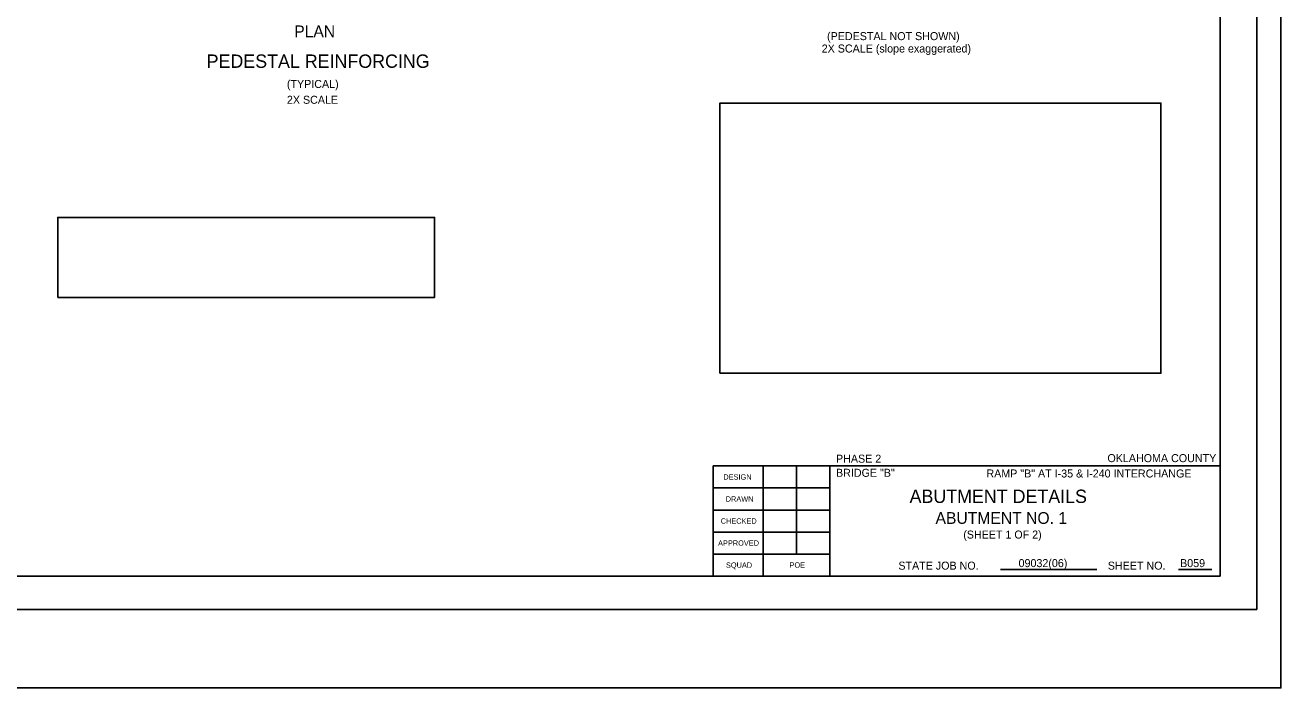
# Model space of a CAD drawing. Extents: x 2146724 to 2153191, y 139029 to 143935.
# Drawn here: x 2146992.9 to 2147068.3, y 143589.8 to 143629.5 of the extents above; entities that cross this region are included whole.
import ezdxf

# ---------------------------------------------------------------- set-up
doc = ezdxf.new("R2010")
doc.units = 0
for name, color, linetype in [('PR_Dimensions', 7, 'Continuous'), ('SHT_Plot_Shape_Full', 7, 'Continuous'), ('SHT_Plot_Shape_Half', 7, 'Continuous'), ('SHT_Sheet_Border', 7, 'Continuous'), ('SHT_Standard_Sheet_Lines', 7, 'Continuous'), ('SHT_Standard_Sheet_Txt', 7, 'Continuous'), ('T', 7, 'Continuous'), ('T-Subtitle', 7, 'Continuous'), ('T-Title', 7, 'Continuous')]:
    doc.layers.add(name, color=color, linetype=linetype)

msp = doc.modelspace()

# ---------------------------------------------------------------- linework, layer by layer
at = {"layer": 'PR_Dimensions'}
for points in [[(2147034.603, 143608.631), (2147061.061, 143608.631), (2147061.061, 143624.83), (2147034.603, 143624.83)], [(2146994.891, 143613.183), (2147017.495, 143613.183), (2147017.495, 143617.975), (2146994.891, 143617.975)]]:
    msp.add_lwpolyline(points, close=True, dxfattribs=at)
at = {"layer": 'SHT_Plot_Shape_Full'}
msp.add_lwpolyline([(2146924.253, 143685.779), (2147068.253, 143685.779), (2147068.253, 143589.779), (2146924.253, 143589.779)], close=True, dxfattribs=at)
at = {"layer": 'SHT_Plot_Shape_Half'}
msp.add_lwpolyline([(2146930.803, 143682.479), (2147066.803, 143682.479), (2147066.803, 143594.479), (2146930.803, 143594.479)], close=True, dxfattribs=at)
at = {"layer": 'SHT_Sheet_Border'}
for p, q in [((2147034.203, 143596.479), (2147034.203, 143603.079)), ((2147034.203, 143603.079), (2147064.603, 143603.079)), ((2147041.203, 143596.479), (2147041.203, 143603.082)), ((2147041.203, 143596.479), (2147041.203, 143603.082))]:
    msp.add_line(p, q, dxfattribs=at)
msp.add_lwpolyline([(2147064.603, 143596.479), (2146938.603, 143596.479), (2146938.603, 143680.479), (2147064.603, 143680.479)], close=True, dxfattribs=at)
at = {"layer": 'SHT_Standard_Sheet_Lines'}
for p, q in [((2147037.203, 143596.479), (2147037.203, 143603.082)), ((2147039.203, 143597.8), (2147039.203, 143603.082)), ((2147051.446, 143596.864), (2147057.207, 143596.864)), ((2147051.446, 143596.864), (2147057.207, 143596.864)), ((2147062.105, 143596.864), (2147064.115, 143596.864)), ((2147062.105, 143596.864), (2147064.115, 143596.864))]:
    msp.add_line(p, q, dxfattribs=at)
for points in [[(2147041.203, 143601.759), (2147034.203, 143601.759)], [(2147041.203, 143600.439), (2147034.203, 143600.439)], [(2147041.203, 143599.119), (2147034.203, 143599.119)], [(2147041.203, 143597.799), (2147034.203, 143597.799)]]:
    msp.add_lwpolyline(points, dxfattribs=at)

# ---------------------------------------------------------------- texts
at = {"layer": 'Defpoints'}
for s, p in [('2X SCALE (slope exaggerated)', (2147040.713, 143627.858)), ('2X SCALE', (2147008.637, 143624.786))]:
    msp.add_text(s, height=0.48, dxfattribs=at).set_placement(p)
at = {"layer": 'SHT_Standard_Sheet_Txt'}
for s, height, p in [('DESIGN', 0.32, (2147034.812, 143602.259)), ('DRAWN', 0.32, (2147034.955, 143600.938)), ('CHECKED', 0.32, (2147034.654, 143599.618)), ('APPROVED', 0.32, (2147034.497, 143598.297)), ('SQUAD', 0.32, (2147034.969, 143596.976)), ('POE', 0.32, (2147038.783, 143596.979)), ('STATE JOB NO.', 0.48, (2147045.311, 143596.864)), ('STATE JOB NO.', 0.48, (2147045.311, 143596.864)), ('SHEET NO. ', 0.48, (2147057.872, 143596.864)), ('SHEET NO. ', 0.48, (2147057.872, 143596.864))]:
    msp.add_text(s, height=height, dxfattribs=at).set_placement(p)
at = {"layer": 'T'}
for s, height, p in [('(PEDESTAL NOT SHOWN)', 0.48, (2147041.034, 143628.601)), ('(TYPICAL)', 0.48, (2147008.637, 143625.734)), ('PHASE 2', 0.48, (2147041.571, 143603.276)), ('OKLAHOMA COUNTY', 0.48, (2147057.85, 143603.308)), ('BRIDGE "B"', 0.48, (2147041.571, 143602.429)), ('RAMP "B" AT I-35 & I-240 INTERCHANGE', 0.48, (2147050.592, 143602.388)), ('(SHEET 1 OF 2)', 0.47917, (2147049.205, 143598.728)), ('09032(06)', 0.48, (2147052.521, 143597.016)), ('B059', 0.48, (2147062.207, 143597.016))]:
    msp.add_text(s, height=height, dxfattribs=at).set_placement(p)
at = {"layer": 'T-Subtitle'}
for s, height, p in [('PLAN', 0.7, (2147009.082, 143628.778)), ('ABUTMENT NO. 1', 0.70312, (2147047.539, 143599.608))]:
    msp.add_text(s, height=height, dxfattribs=at).set_placement(p)
at = {"layer": 'T-Title'}
for s, height, p in [('PEDESTAL REINFORCING', 0.8, (2147003.823, 143626.94)), ('ABUTMENT DETAILS', 0.79999, (2147045.982, 143600.86))]:
    msp.add_text(s, height=height, dxfattribs=at).set_placement(p)

doc.saveas('drawing.dxf')
